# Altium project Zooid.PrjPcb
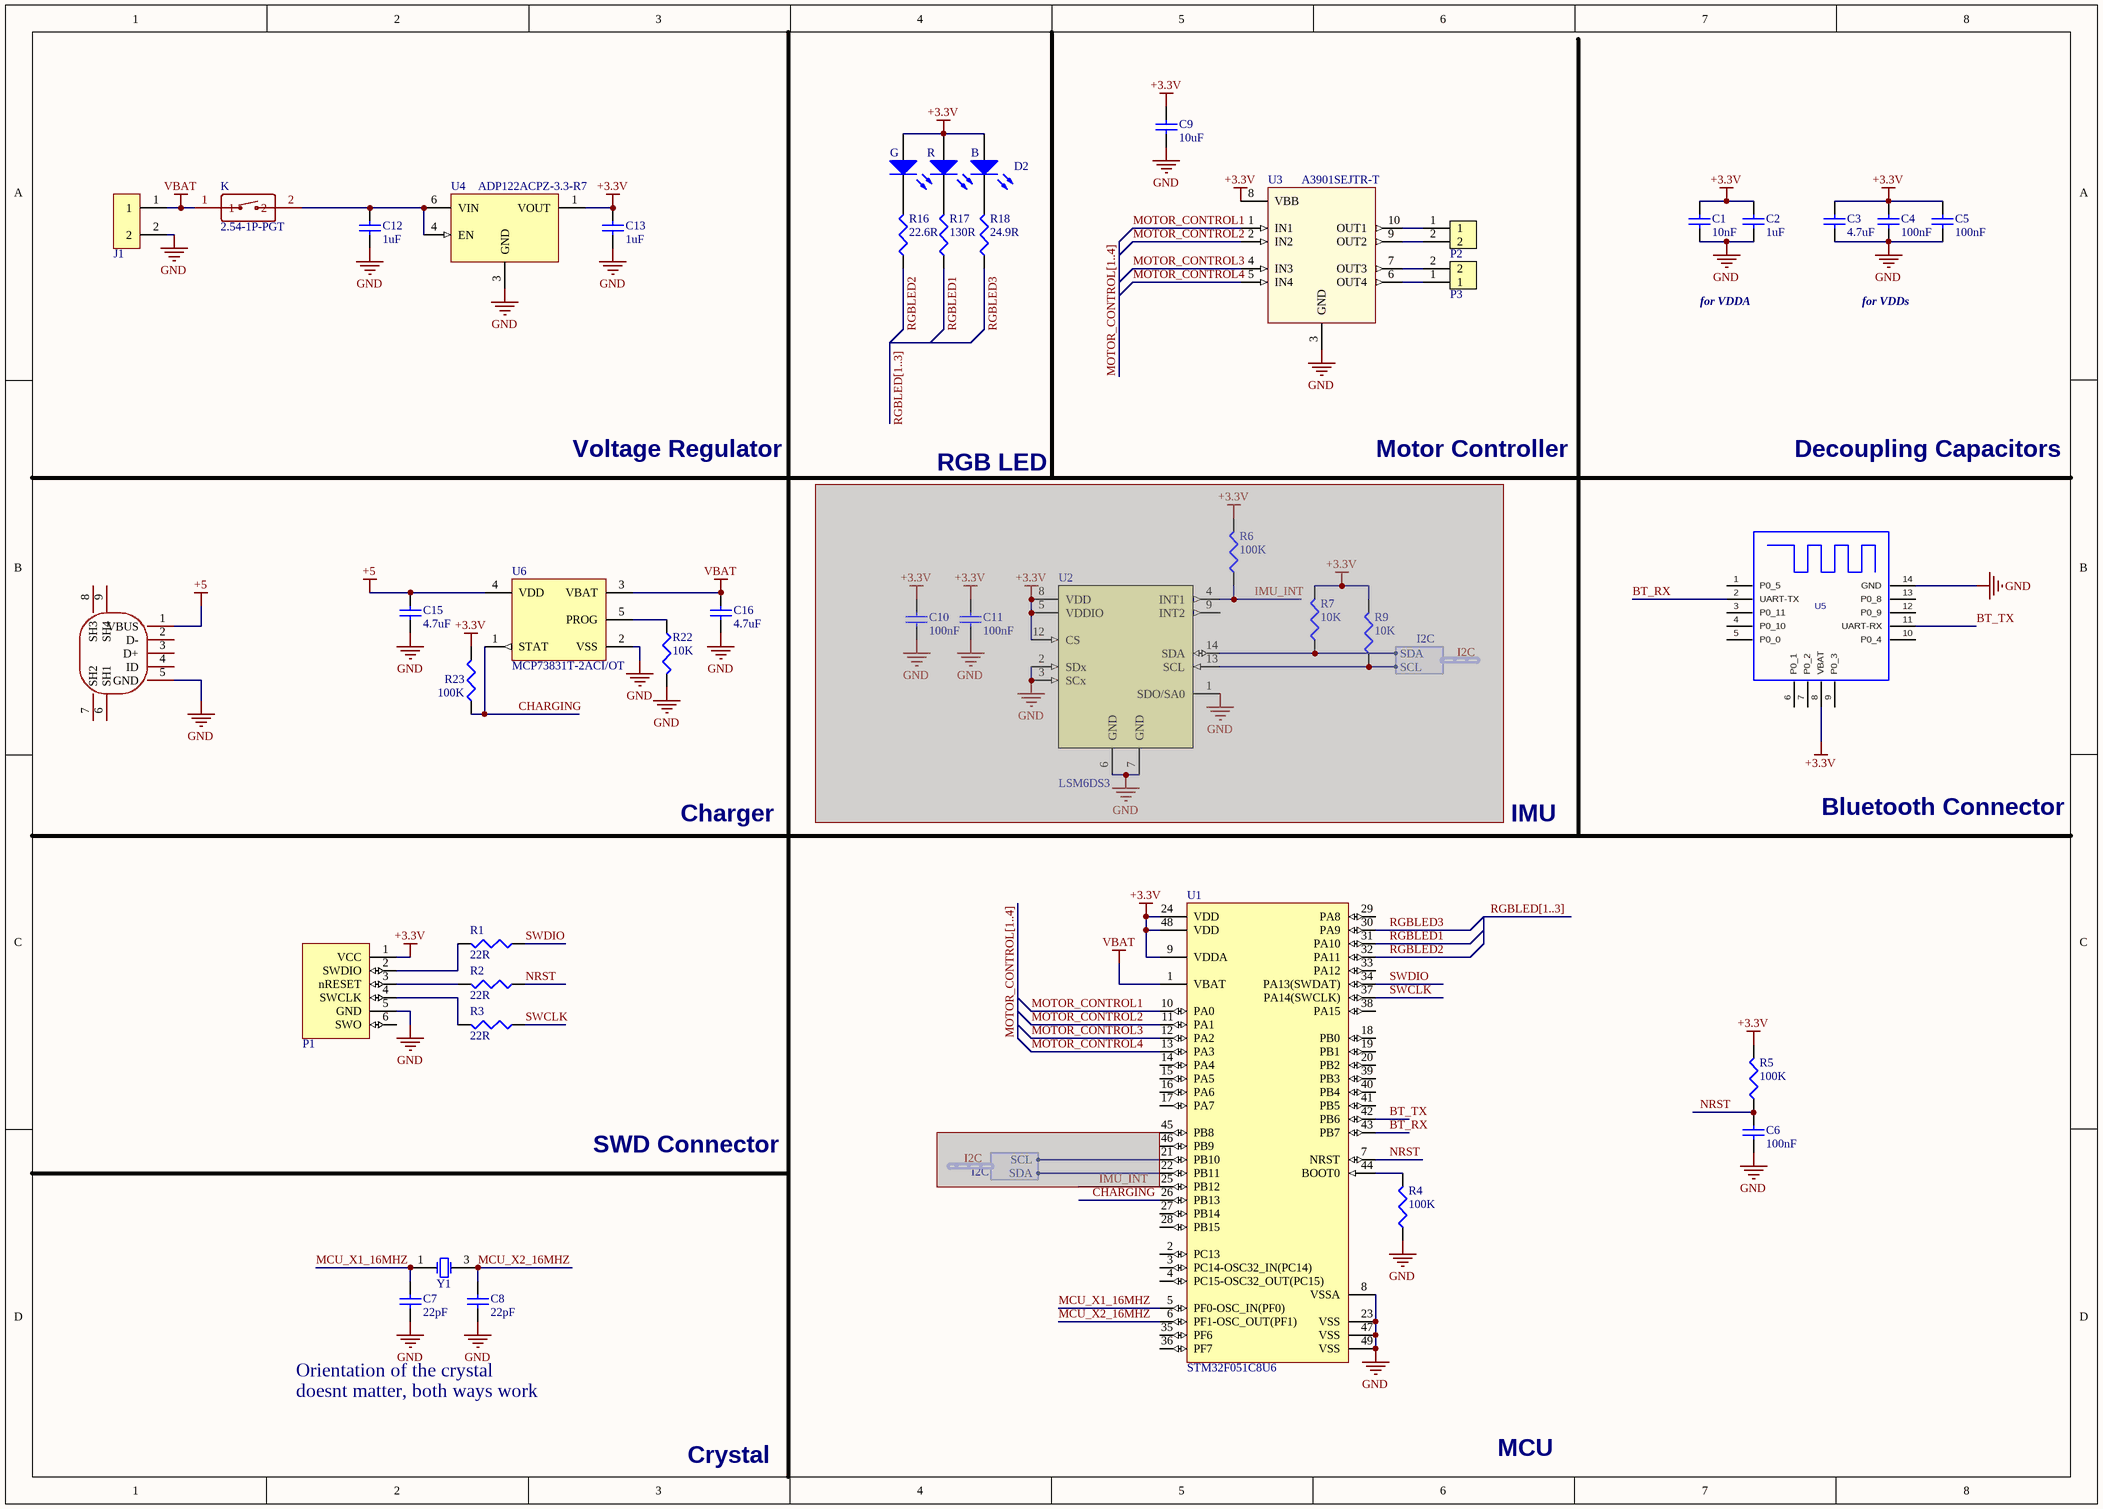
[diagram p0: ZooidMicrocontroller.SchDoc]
1 sheet, 42 parts. Net scope: global (net labels, ports and power ports of the same name join across sheets).
Board files: PCB1.PcbDoc, PCB2.PcbDoc, PCB3.PcbDoc

## Sheet ZooidMicrocontroller.SchDoc
size A3

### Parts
C1  10nF  [0402]
C2  1uF  [0603]
C3  4.7uF  [0603]
C4  100nF  [0402]
C5  100nF  [0402]
C6  100nF  [0402]
C7  22pF  [0402]
C8  22pF  [0402]
C9  10uF  [0603]
C10  100nF  [0402]  (masked out: inside a compile mask, not in the netlist)
C11  100nF  [0402]  (masked out: inside a compile mask, not in the netlist)
C12  1uF  [0603]
C13  1uF  [0603]
C15  4.7uF  [0603]
C16  4.7uF  [0603]
D2  SMLVN6RGB1W1  [3.5x2.8 mm 6-SMD]  (value not drawn)
J1  78171-0002  [HDR1*2]  (value not drawn)
K  2.54-1P-PGT  [SW-SMD_2P-L6.2-LS9.4]
P1  TC2030-IDC-NL  [TC2030-IDC-NL]  (value not drawn)
P2  HEADER 2X1 0.05" UNPOLARIZED  [HDR1*2]  (value not drawn)
P3  HEADER 2X1 0.05" UNPOLARIZED  [HDR1*2]  (value not drawn)
R1  22R  [0402]
R2  22R  [0402]
R3  22R  [0402]
R4  100K  [0402]
R5  100K  [0402]
R6  100K  [0402]  (masked out: inside a compile mask, not in the netlist)
R7  10K  [0402]  (masked out: inside a compile mask, not in the netlist)
R9  10K  [0402]  (masked out: inside a compile mask, not in the netlist)
R16  22.6R  [0402]
R17  130R  [0402]
R18  24.9R  [0402]
R22  10K  [0402]
R23  100K  [0402]
U1  STM32F051C8U6  [QFN50P700X700X60_HS-49L]
U2  LSM6DS3  [LGA-14 2.5x3x0.86 mm 14L]  (masked out: inside a compile mask, not in the netlist)
U3  A3901SEJTR-T  [DFN50P300X300X75_HS-11N]
U4  ADP122ACPZ-3.3-R7  [LFCSP-6 2.0X2.0X0.55]
U5  DX-BT24-T  [DX-BT24-T]  (value not drawn)
U6  MCP73831T-2ACI/OT  [SOT-23-OT5_L]
USB  MicroXNJ  [MICRO-USB-SMD_MICROXNJ]  (value not drawn)
Y1  7V-16.000MAAE-T  [3.2x2.5 CRYSTAL]  (value not drawn)

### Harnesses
I2C: SDA, SCL

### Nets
+3.3V: C1.2 C2.2 C3.2 C4.2 C5.2 C9.2 C13.2 D2.1(AB) D2.2(AR) D2.3(AG) P1.1(VCC) R5.2 R23.2 U1.9(VDDA) U1.24(VDD) U1.48(VDD) U3.8(VBB) U4.1(VOUT) U5.8(VBAT)
+5: C15.2 U6.4(VDD) USB.1(VBUS)
GND: C1.1 C2.1 C3.1 C4.1 C5.1 C6.1 C7.1 C8.1 C9.1 C12.1 C13.1 C15.1 C16.1 J1.2 P1.5(GND) R4.1 R22.2 U1.8(VSSA) U1.23(VSS) U1.47(VSS) U1.49(VSS) U3.3(GND) U3.11(PAD) U4.2(NC) U4.3(GND) U4.5(NC) U4.7(THPAD) U5.14(GND) U6.2(VSS) USB.5(GND) Y1.2(GND) Y1.4(GND)
VBAT: C16.2 J1.1 K.1 U1.1(VBAT) U6.3(VBAT)
BT_RX: U1.43(PB7) U5.2(UART-TX)
BT_TX: U1.42(PB6) U5.11(UART-RX)
CHARGING: R23.1 U1.26(PB13) U6.1(STAT)
MCU_X1_16MHZ: C7.2 U1.5(PF0-OSC_IN(PF0)) Y1.1(X1)
MCU_X2_16MHZ: C8.2 U1.6(PF1-OSC_OUT(PF1)) Y1.3(X2)
MOTOR_CONTROL1: U1.10(PA0) U3.1(IN1)
MOTOR_CONTROL2: U1.11(PA1) U3.2(IN2)
MOTOR_CONTROL3: U1.12(PA2) U3.4(IN3)
MOTOR_CONTROL4: U1.13(PA3) U3.5(IN4)
NRST: C6.2 R2.1 R5.1 U1.7(NRST)
RGBLED1: R17.1 U1.31(PA10)
RGBLED2: R16.1 U1.32(PA11)
RGBLED3: R18.1 U1.30(PA9)
SWCLK: R3.1 U1.37(PA14(SWCLK))
SWDIO: R1.1 U1.34(PA13(SWDAT))
NetC12_2: C12.2 K.2 U4.4(EN) U4.6(VIN)
NetD2_4: D2.4(KG) R16.2
NetD2_5: D2.5(KR) R17.2
NetD2_6: D2.6(KB) R18.2
NetP1_2: P1.2(SWDIO) R1.2
NetP1_3: P1.3(nRESET) R2.2
NetP1_4: P1.4(SWCLK) R3.2
NetP2_1: P2.1 U3.10(OUT1)
NetP2_2: P2.2 U3.9(OUT2)
NetP3_1: P3.1 U3.6(OUT4)
NetP3_2: P3.2 U3.7(OUT3)
NetR4_2: R4.2 U1.44(BOOT0)
NetR22_1: R22.1 U6.5(PROG)

Not connected (* = marked no-connect by the designer): P1 6(SWO); U1 2(PC13) 3(PC14-OSC32_IN(PC14)) 4(PC15-OSC32_OUT(PC15)) 14(PA4) 15(PA5) 16(PA6) 17(PA7) 18(PB0) 19(PB1) 20(PB2) 21(PB10) 22(PB11) 25(PB12) 27(PB14) 28(PB15) 29(PA8) 33(PA12) 35(PF6) 36(PF7) 38(PA15) 39(PB3) 40(PB4) 41(PB5) 45(PB8) 46(PB9); U5 1(P0_5) 3(P0_11) 4(P0_10) 5(P0_0) 6(P0_1) 7(P0_2) 9(P0_3) 10(P0_4) 12(P0_9) 13(P0_8); USB 2(D-) 3(D+) 4(ID) 6(SH1) 7(SH2) 8(SH3) 9(SH4)

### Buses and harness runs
bus MOTOR_CONTROL[1..4]
bus RGBLED[1..3]

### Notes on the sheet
- for VDDA
- for VDDs
- Voltage Regulator
- RGB LED
- Motor Controller
- Decoupling Capacitors
- Charger
- IMU
- Bluetooth Connector
- SWD Connector
- Orientation of the crystal
- doesnt matter, both ways work
- MCU
- Crystal

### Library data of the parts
C1 = 10nF: 10nF 0402 X7R 25V ±5%
C2 C12 C13 = 1uF: 1uF 0603 X5R 10V ±10%
C3 C15 C16 = 4.7uF: 4.7uF 0603 X5R 10V ±10%
C4-C6 C10 C11 = 100nF: 100nF 0402 X7R 16V ±10%
C7 C8 = 22pF: 22pF 0402 NP0/CG0 50V ±5%
C9 = 10uF: 10uF 0603 X5R 6.3V ±20%
D2 = SMLVN6RGB1W1: ROHM SMLVN6RGB1W1 LED Tri-Color Blue/Green/Red Chip LED 6-Pin 1411 T/RLED Tri-Color Blue/Green/Red Chip LED 6-Pin 1411
J1 = 78171-0002: Molex Pico-EZmate™ Wire-to-Board Header, 2 contacts
P1 = TC2030-IDC-NL: TagConnect TC2030-IDC-NL SWD Programming Connector
R1-R3 = 22R: 22R 0402 1/16W ±1%
R4-R6 R23 = 100K: 100K 0402 1/16W ±1%
R7 R9 R22 = 10K: 10K 0402 1/16W ±1%
R16 = 22.6R: 22.6R 0402 1/16W ±0.05R
R17 = 130R: 130R 0402 1/16W ±0.05R
R18 = 24.9R: 24.9R 0402 1/16W ±0.05R
U1 = STM32F051C8U6: STMICROELECTRONICS  STM32F051C8U6  MCU 32BIT CORTEX-M0 48MHZ UFQFPN-48
U2 = LSM6DS3: STMicroelectronics iNEMO inertial module:   3D accelerometer and 3D gyroscope
U3 = A3901SEJTR-T: ALLEGRO MICROSYSTEMS - A3901SEJTR-T - IC, MOTOR DRIVER
U4 = ADP122ACPZ-3.3-R7: Analog Devices ADP122ACPZ-3.3-R7 - 5.5 V Input, 300 mA, Low Quiescent  Current, CMOS Linear Regulator
U5 = DX-BT24-T: PCB DECAL: DX-BT24-S
U6 = MCP73831T-2ACI/OT: Miniature Single-Cell, Fully Integrated Li-Ion, Li-Polymer Charge Management Controller, 4.2V, 5-Pin SOT-23, Industrial Temperature, Tape and Reel
USB = MicroXNJ: Manufacturer: SHOU HAN(首韩); Add into BOM: yes; Connector Type: Micro-B; Gender: 母; Number of Contacts: 5P; Number of Ports: 1; Current Rating - Power (Max): 1.8A; Rated Voltage (Max): 30V; Connect-Disconnect Life: 5千次; Core Colour: 黑色
Y1 = 7V-16.000MAAE-T: TXC - 7V-16.000MAAE-T, 16MHZ, 30PPM, 12PF - CRYSTAL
